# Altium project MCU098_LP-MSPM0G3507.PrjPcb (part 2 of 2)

## Sheet MCU098_04_XDS110-ET_EnergyTrace.SchDoc: XDS110-ET EnergyTrace
size 431 x 279 mm; Date: Not shown in title block; ApprovedBy: Not shown in title block; CheckedBy: Not shown in title block; Author: Not shown in title block; CompanyName: Not shown in title block; DrawnBy: Johnson He; Engineer: Not shown in title block; Organization: Not shown in title block; Address1: Not shown in title block; Address2: Not shown in title block; Address3: Not shown in title block; Address4: Not shown in title block; DocumentNumber: 2; Revision: Use project parameter SCH_Rev; SheetNumber: 4; SheetTotal: 7; PageSetup: Record=PageOptions¦CenterHorizontal=True¦CenterVertical=True¦PrintScale=1.00¦XCorrection=1.00¦YCorrection=1.00¦PrintKind=0¦BorderSize=5000000¦LeftOffset=0¦BottomOffset=0¦Orientation=2¦PaperLength=1000¦PaperWidth=1000¦Scale=100¦PaperSource=15¦PrintQuality=600¦MediaType=1¦DitherType=10¦PaperKind=Letter¦PrintScaleMode=1
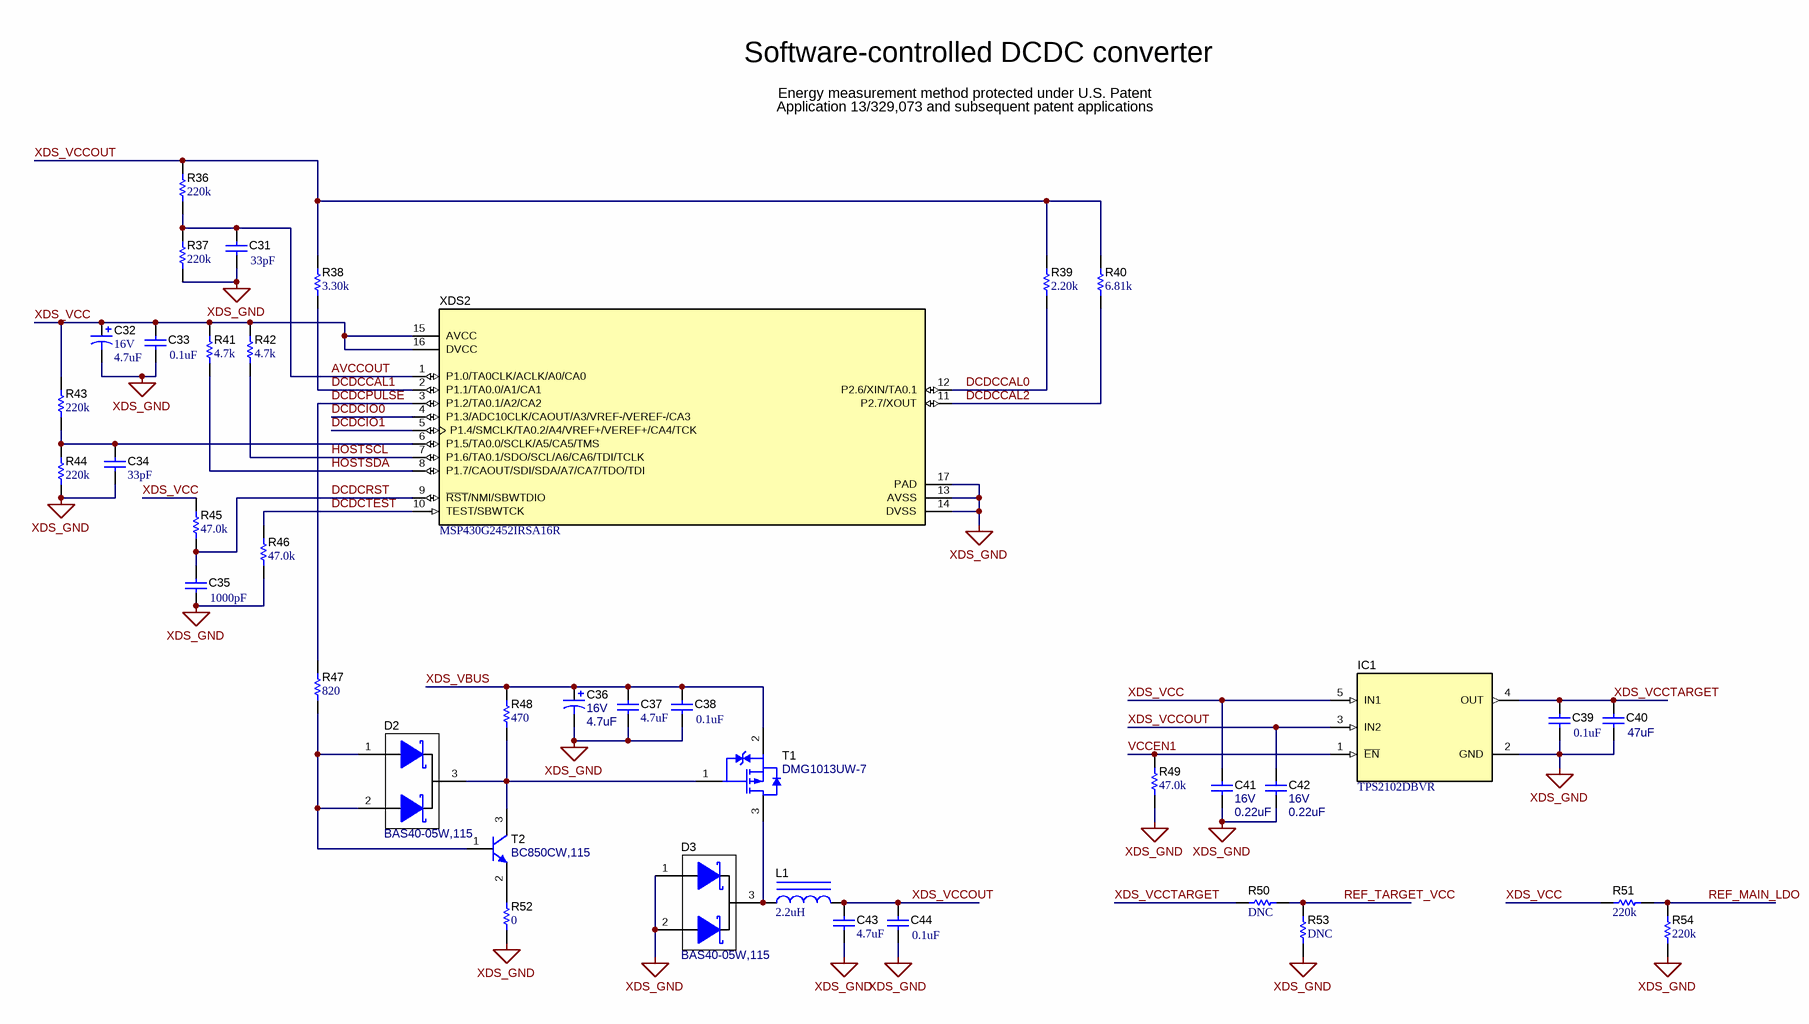
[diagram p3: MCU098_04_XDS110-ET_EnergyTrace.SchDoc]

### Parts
C31  ValueDisplayed: 33pF  [0402]  (hidden comment: GRM1555C1H330JA01D)
C32  VDC_V: 16V  ValueDisplayed: 4.7uF  [3216-18]  (hidden comment: TAJA475K016RNJ)
C33  ValueDisplayed: 0.1uF  [0402]  (hidden comment: GRM155R70J104KA01D)
C34  ValueDisplayed: 33pF  [0402]  (hidden comment: GRM1555C1H330JA01D)
C35  ValueDisplayed: 1000pF  [0402]  (hidden comment: GCM155R71H102KA37D)
C36  VDC_V: 16V  ValueDisplayed: 4.7uF  [3216-18]  (hidden comment: TAJA475K016RNJ)
C37  ValueDisplayed: 4.7uF  [0603]  (hidden comment: GRM188R61C475KAAJ)
C38  ValueDisplayed: 0.1uF  [0402]  (hidden comment: GRM155R70J104KA01D)
C39  ValueDisplayed: 0.1uF  [0402]  (hidden comment: GRM155R70J104KA01D)
C40  ValueDisplayed: 47uF  [0603]  (hidden comment: GRM188R60J476ME15D)
C41  VDC_V: 16V  ValueDisplayed: 0.22uF  [0402]  (hidden comment: GRM155R71C224KA12D)
C42  VDC_V: 16V  ValueDisplayed: 0.22uF  [0402]  (hidden comment: GRM155R71C224KA12D)
C43  ValueDisplayed: 4.7uF  [0603]  (hidden comment: GRM188R61C475KAAJ)
C44  ValueDisplayed: 0.1uF  [0402]  (hidden comment: GRM155R70J104KA01D)
D2  BAS40-05W,115  [SOT-323]
D3  BAS40-05W,115  [SOT-323]
IC1  TPS2102DBVR  [DBV0005A_N]
L1  ValueDisplayed: 2.2uH  [CBC2518]  (hidden comment: CBC2518T2R2M)
R36  ValueDisplayed: 220k  [0402]  (hidden comment: RC0402FR-07220KL)
R37  ValueDisplayed: 220k  [0402]  (hidden comment: RC0402FR-07220KL)
R38  ValueDisplayed: 3.30k  [0402]  (hidden comment: ERJ-2RKF3301X)
R39  ValueDisplayed: 2.20k  [0402]  (hidden comment: CRCW04022K20FKED)
R40  ValueDisplayed: 6.81k  [0402]  (hidden comment: CRCW04026K81FKED)
R41  ValueDisplayed: 4.7k  [0402]  (hidden comment: CRCW04024K70JNED)
R42  ValueDisplayed: 4.7k  [0402]  (hidden comment: CRCW04024K70JNED)
R43  ValueDisplayed: 220k  [0402]  (hidden comment: RC0402FR-07220KL)
R44  ValueDisplayed: 220k  [0402]  (hidden comment: RC0402FR-07220KL)
R45  ValueDisplayed: 47.0k  [0402]  (hidden comment: RC0402FR-0747KL)
R46  ValueDisplayed: 47.0k  [0402]  (hidden comment: RC0402FR-0747KL)
R47  ValueDisplayed: 820  [0402]  (hidden comment: RC0402FR-07820RL)
R48  ValueDisplayed: 470  [0402]  (hidden comment: CRCW0402470RJNED)
R49  ValueDisplayed: 47.0k  [0402]  (hidden comment: RC0402FR-0747KL)
R50  ValueDisplayed: DNC  [0402]  (hidden comment: RC0402FR-07220KL)  (no BOM)
R51  ValueDisplayed: 220k  [0402]  (hidden comment: RC0402FR-07220KL)
R52  ValueDisplayed: 0  [0603]  (hidden comment: RC0603JR-070RL)
R53  ValueDisplayed: DNC  [0402]  (hidden comment: RC0402FR-07220KL)  (no BOM)
R54  ValueDisplayed: 220k  [0402]  (hidden comment: RC0402FR-07220KL)
T1  DMG1013UW-7  [SOT-323]
T2  BC850CW,115  [SOT-323]
XDS2  MSP430G2452IRSA16R  [RSA0016B]

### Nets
XDS_GND: C31.2 C32.2(-) C33.2 C34.2 C35.2 C36.2(-) C37.1 C38.2 C39.2 C40.2 C41.2 C42.2 C43.1 C44.2 D3.1(A) D3.2(A) IC1.2(GND) R37.1 R44.1 R46.1 R49.1 R52.1 R53.1 R54.1 XDS2.13(AVSS) XDS2.14(DVSS) XDS2.17(PAD)
XDS_VCC: C32.1(+) C33.1 C41.1 IC1.5(IN1) R41.2 R42.2 R43.2 R45.2 R51.2 XDS2.15(AVCC) XDS2.16(DVCC)
AVCCOUT: C31.1 R36.1 R37.2 XDS2.1(P1.0/TA0CLK/ACLK/A0/CA0)
DCDCCAL0: R39.1 XDS2.12(P2.6/XIN/TA0.1)
DCDCCAL1: R38.1 XDS2.2(P1.1/TA0.0/A1/CA1)
DCDCCAL2: R40.1 XDS2.11(P2.7/XOUT)
DCDCIO0: XDS2.4(P1.3/ADC10CLK/CAOUT/A3/VREF-/VEREF-/CA3)
DCDCIO1: XDS2.5(P1.4/SMCLK/TA0.2/A4/VREF+/VEREF+/CA4/TCK)
DCDCPULSE: R47.2 XDS2.3(P1.2/TA0.1/A2/CA2)
DCDCRST: C35.1 R45.1 XDS2.9(~{RST}/NMI/SBWTDIO)
DCDCTEST: R46.2 XDS2.10(TEST/SBWTCK)
HOSTSCL: R42.1 XDS2.7(P1.6/TA0.1/SDO/SCL/A6/CA6/TDI/TCLK)
HOSTSDA: R41.1 XDS2.8(P1.7/CAOUT/SDI/SDA/A7/CA7/TDO/TDI)
REF_MAIN_LDO: R51.1 R54.2
REF_TARGET_VCC: R50.1 R53.2
VCCEN1: IC1.1(~{EN}) R49.2
XDS_VBUS: C36.1(+) C37.2 C38.1 R48.2 T1.2(S)
XDS_VCCOUT: C42.1 C43.2 C44.1 IC1.3(IN2) L1.2 R36.2 R38.2 R39.2 R40.2
XDS_VCCTARGET: C39.1 C40.1 IC1.4(OUT) R50.2
NetC34_1: C34.1 R43.1 R44.2 XDS2.6(P1.5/TA0.0/SCLK/A5/CA5/TMS)
NetD2_1: D2.1(A) D2.2(A) R47.1 T2.1(B)
NetD2_3: D2.3(K) R48.1 T1.1(G) T2.3(C)
NetD3_3: D3.3(K) L1.1 T1.3(D)
NetR52_2: R52.2 T2.2(E)

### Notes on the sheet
- Software-controlled DCDC converter
- Energy measurement method protected under U.S. Patent
- Application 13/329,073 and subsequent patent applications

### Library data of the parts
C31 C34 = CMP-0006454-1: CAP, CERM, 33 pF, 50 V, +/- 5%, C0G/NP0, 0402; Manufacturer: MuRata; TaMin_C: -55°C; Polarized: N; SizeAreaWB_mm2: 3; Value1: Unknown; U/M: EA; Value: 33pF; TaMax_C: 125°C; SizeZ_mm: 0.6; SizeX_mm: 1; SizeY_mm: 0.5; Value2: 50V; AEC Category: Q200
C32 C36 = CMP-0011480-1: CAP, TA, 4.7 uF, 16 V, +/- 10%, 4 ohm, SMD; Manufacturer: AVX; TaMin_C: -55°C; ESR_ohm: 4; Polarized: Y; SizeAreaWB_mm2: 10.92; Value1: 4 ohm; U/M: EA; Value: 4.7uF; TaMax_C: 125°C; SizeZ_mm: 1.8; SizeX_mm: 3.2; SizeY_mm: 1.6; SizeArea_mm2: 5.12; CompType: Capacitor; AEC Qualified: N; Cap_F: 4.7µF; AEC Category: Q200
C33 C38 C39 C44 = CMP-0006623-2: CAP, CERM, 0.1 uF, 6.3 V, +/- 10%, X7R, 0402; Manufacturer: MuRata; TaMin_C: -55°C; Polarized: N; SizeAreaWB_mm2: 3; Value1: Unknown; U/M: EA; Value: 0.1uF; TaMax_C: 125°C; SizeZ_mm: 0.6; SizeX_mm: 1; SizeY_mm: 0.5; Value2: 6.3V; Cap_F: 100nF; AEC Category: Q200
C35 = CMP-0006354-2: CAP, CERM, 1000 pF, 50 V, +/- 10%, X7R, AEC-Q200 Grade 1, 0402; Manufacturer: MuRata; TaMin_C: -55°C; Polarized: N; SizeAreaWB_mm2: 3; Value1: Unknown; U/M: EA; Value: 1000pF; TaMax_C: 125°C; SizeZ_mm: 0.6; SizeX_mm: 1; SizeY_mm: 0.5; Value2: 50V; AEC Qualified: Y; Cap_F: 1nF; AEC Category: Q200
C37 C43 = CMP-0007341-4: CAP, CERM, 4.7 uF, 16 V, +/- 10%, X5R, 0603; Manufacturer: MuRata; TaMin_C: -55°C; Polarized: N; SizeAreaWB_mm2: 4.68; Value1: Unknown; U/M: EA; Value: 4.7uF; TaMax_C: 85°C; SizeZ_mm: 1; SizeX_mm: 1.6; SizeY_mm: 0.8; Value2: 16V; SizeArea_mm2: 1.28; Cap_F: 4.7µF; AEC Category: Q200
C40 = CMP-0007313-1: CAP, CERM, 47 uF, 6.3 V, +/- 20%, X5R, 0603; Manufacturer: MuRata; TaMin_C: -55°C; Polarized: N; SizeAreaWB_mm2: 4.68; Value1: Unknown; U/M: EA; Value: 47uF; TaMax_C: 85°C; SizeZ_mm: 1; SizeX_mm: 1.6; SizeY_mm: 0.8; Value2: 6.3V; SizeArea_mm2: 1.28; Cap_F: 47µF; AEC Category: Q200
C41 C42 = CMP-0006648-1: CAP, CERM, 0.22 uF, 16 V, +/- 10%, X7R, 0402; Manufacturer: MuRata; TaMin_C: -55°C; Polarized: N; SizeAreaWB_mm2: 3; Value1: Unknown; U/M: EA; Value: 0.22uF; TaMax_C: 125°C; SizeZ_mm: 0.6; SizeX_mm: 1; SizeY_mm: 0.5; Cap_F: 220nF; AEC Category: Q200
D2 D3 = CMP-0028883-1: Diode, Schottky, 40 V, 0.12 A, AEC-Q101, SOT-323; Manufacturer: Nexperia; Io_A: 120mA; Green_Lifecycle: Not Set; SizeAreaWB_mm2: 10.24; Vr_V: 40V; Green_REACh: Incomplete; Value1: 0.12A; TJmax_C: 150°C; U/M: EA; Value: 40V; SizeZ_mm: 1.1; SizeX_mm: 2.2; Vf_V: 1V; SizeArea_mm2: 4.84; AEC Qualified: Y; AEC Category: Q101
IC1 = CMP-0074212-1: 2.7-4V Dual In/Single Out MOSFET, 0.5A Main/0.1A Aux Input, Act-Low Enable, Comm. Temp., DBV0005A (SOT-23-5); Alternate PartNumber: TPS2102DBVT; Alternate Manufacturer: Texas Instruments; SizeAreaWB_mm2: 14.82; U/M: EA; SizeZ_mm: 1.45; SizeX_mm: 2.8; SizeY_mm: 2.9; SizeArea_mm2: 8.12; CompType: IC
L1 = CMP-0059590-1: Inductor, Wirewound, Ceramic, 2.2 uH, 0.89 A, 0.13 ohm, SMD; Manufacturer: Taiyo Yuden; Isat: 0.89A @ 30% inductance drop; Irms: 1.1A @ 40C rise; Green_Lifecycle: Active; SizeAreaWB_mm2: 9.8; DCR_ohm: 0.13; Green_REACh: Passed; Value: 2.2uH; Imax_A: 890mA; SizeZ_mm: 1.8; SizeX_mm: 2.5; Value2: 0.89A; SizeArea_mm2: 4.5; Ind_H: 2.2µH; AEC Qualified: N; AEC Category: Q200
R36 R37 R43 R44 R51 R54 = CMP-0026728-1: RES, 220 k, 1%, 0.0625 W, 0402; Manufacturer: Yageo America; Power_W: 62.5mW; TempCo: 100 ppm/C; U/M: EA; Value: 220k; SizeX_mm: 1; SizeY_mm: 0.5; SizeZ_mm: 0.6; AEC Qualified: N; VDC_V: 50V; AEC Category: Q200
R38 = CMP-0026695-1: RES, 3.30 k, 1%, 0.1 W, AEC-Q200 Grade 0, 0402; Manufacturer: Panasonic; Power_W: 100mW; TempCo: 100 ppm/C; Value_Code: 3k30; U/M: EA; Value: 3.30k; Res_ohm: 3.3k; SizeX_mm: 1; SizeY_mm: 0.5; SizeZ_mm: 0.6; Value2: 0.1W; AEC Qualified: Y; VDC_V: 50V; AEC Grade: 0; AEC Category: Q200
R39 = CMP-0026231-1: RES, 2.20 k, 1%, 0.063 W, 0402; Manufacturer: Vishay-Dale; Power_W: 63mW; TempCo: 100 ppm/C; Value_Code: 2k20; U/M: EA; Value: 2.20k; Res_ohm: 2.2k; SizeX_mm: 1; SizeY_mm: 0.5; SizeZ_mm: 0.6; Value2: 0.063W; AEC Category: Q200
R40 = CMP-0026517-1: RES, 6.81 k, 1%, 0.063 W, 0402; Manufacturer: Vishay-Dale; Power_W: 63mW; TempCo: 100 ppm/C; Value_Code: 6k81; U/M: EA; Value: 6.81k; EIA_Code: E96; SizeX_mm: 1; SizeY_mm: 0.5; SizeZ_mm: 0.6; Value2: 0.063W; VDC_V: 50V; AEC Category: Q200
R41 R42 = CMP-0026938-1: RES, 4.7 k, 5%, 0.063 W, 0402; Manufacturer: Vishay-Dale; Power_W: 63mW; TempCo: 200 ppm/C; Value_Code: 4k70; U/M: EA; Value: 4.7k; EIA_Code: E24; SizeX_mm: 1; SizeY_mm: 0.5; SizeZ_mm: 0.6; Value2: 0.063W; VDC_V: 50V; AEC Category: Q200
R45 R46 R49 = CMP-0026737-1: RES, 47.0 k, 1%, 0.0625 W, 0402; Manufacturer: Yageo America; Power_W: 62.5mW; TempCo: 100 ppm/C; Value_Code: 47k0; U/M: EA; Value: 47.0k; Res_ohm: 47k; SizeX_mm: 1; SizeY_mm: 0.5; SizeZ_mm: 0.6; AEC Qualified: N; VDC_V: 50V; AEC Category: Q200
R47 = CMP-0026743-1: RES, 820, 1%, 0.063 W, 0402; Manufacturer: Yageo America; Power_W: 63mW; TempCo: 100 ppm/C; Value_Code: 820R; U/M: EA; Value: 820; SizeX_mm: 1; SizeY_mm: 0.5; SizeZ_mm: 0.6; Value2: 0.063W; AEC Qualified: N; VDC_V: 50V; AEC Category: Q200
R48 = CMP-0026934-1: RES, 470, 5%, 0.063 W, 0402; Manufacturer: Vishay-Dale; Power_W: 63mW; TempCo: 200 ppm/C; Value_Code: 470R; U/M: EA; Value: 470; EIA_Code: E24; SizeX_mm: 1; SizeY_mm: 0.5; SizeZ_mm: 0.6; Value2: 0.063W; VDC_V: 50V; AEC Category: Q200
R50 R53 = CMP-0026728-1: RES, 220 k, 1%, 0.0625 W, 0402; Manufacturer: Yageo America; Power_W: 62.5mW; TempCo: 100 ppm/C; Value_Code: 220k; U/M: EA; Value: 220k; SizeX_mm: 1; SizeY_mm: 0.5; SizeZ_mm: 0.6; AEC Qualified: N; VDC_V: 50V; AEC Category: Q200
R52 = CMP-0025885-5: RES, 0, 5%, 0.1 W, 0603; Manufacturer: Yageo; Power_W: 100mW; TempCo: 200 ppm/C; Value_Code: 0000; Value: 0; EIA_Code: E24; SizeX_mm: 1.6; SizeZ_mm: 1; Value2: 0.1W; SizeArea_mm2: 1.28; AEC Qualified: N; VDC_V: 75V; AEC Category: Q200; SizeY_mm: 0.8; SizeAreaWB_mm2: 4.68
T1 = CMP-0000035-1: MOSFET, P-CH, -20 V, -0.82 A, SOT-323; Alternate Manufacturer: None; Manufacturer: Diodes Inc.; SizeZ_mm: 1.1; ChType: P; Value2: 0.622 nC; Value1: 0.7; VdsMax_V: -20V; SizeX_mm: 2.2; Vgs_V: -6V; Value: -20V; Rdson45_ohm: 0.75; SizeArea_mm2: 4.84; AEC Category: Q101; IdsMax_A: -820mA; SizeAreaWB_mm2: 10.24; U/M: EA; QgTyp_nC: 0.622
T2 = CMP-0000466-1: Transistor, NPN, 45 V, 0.1 A, SOT-323; Manufacturer: NXP Semiconductor; TaMax_C: 150°C; Value2: 800; Value1: 0.1 A; Vcesat1_V: 250mV; SizeX_mm: 2.2; TaMin_C: -65°C; IcRated_A: 100mA; CompType: BJT; SizeZ_mm: 1.1; Value: 45 V; SizeArea_mm2: 4.84; NPN: 1; Vceo_V: 45V; PNP: 0; AEC Category: Q101; SizeAreaWB_mm2: 10.24; U/M: EA
XDS2 = CMP-0039611-2: MSP430G2x52, MSP430G2x12 Mixed Signal Microcontroller, RSA0016B (VQFN-16); Manufacturer: Texas Instruments; Alternate PartNumber: MSP430G2452IRSA16T; Eco-Plan: Green (RoHS & no Sb/Br); ADC: 10-bit SAR; SRAM(B): 256; Temp Sensor: Yes; Frequency(MHz): 16; ADC Channels: 8; Timers - 16-bit: 1; AEC Category: Q200; AEC Qualified: N; CompType: IC; Rating: Catalog; SizeAreaWB_mm2: 25; SizeX_mm: 4

## Sheet MCU098_05_XDS110_Target_Interface.SchDoc: XDS110-ET Interface
size 431 x 279 mm; DrawnBy: Johnson He; SheetNumber: 5; SheetTotal: 7; PageSetup: Record=PageOptions¦CenterHorizontal=True¦CenterVertical=True¦PrintScale=0.97¦XCorrection=1.00¦YCorrection=1.00¦PrintKind=0¦BorderSize=5000000¦LeftOffset=0¦BottomOffset=0¦Orientation=2¦PaperLength=1000¦PaperWidth=1000¦Scale=100¦PaperSource=15¦PrintQuality=600¦MediaType=1¦DitherType=10¦PaperKind=Letter¦PrintScaleMode=1
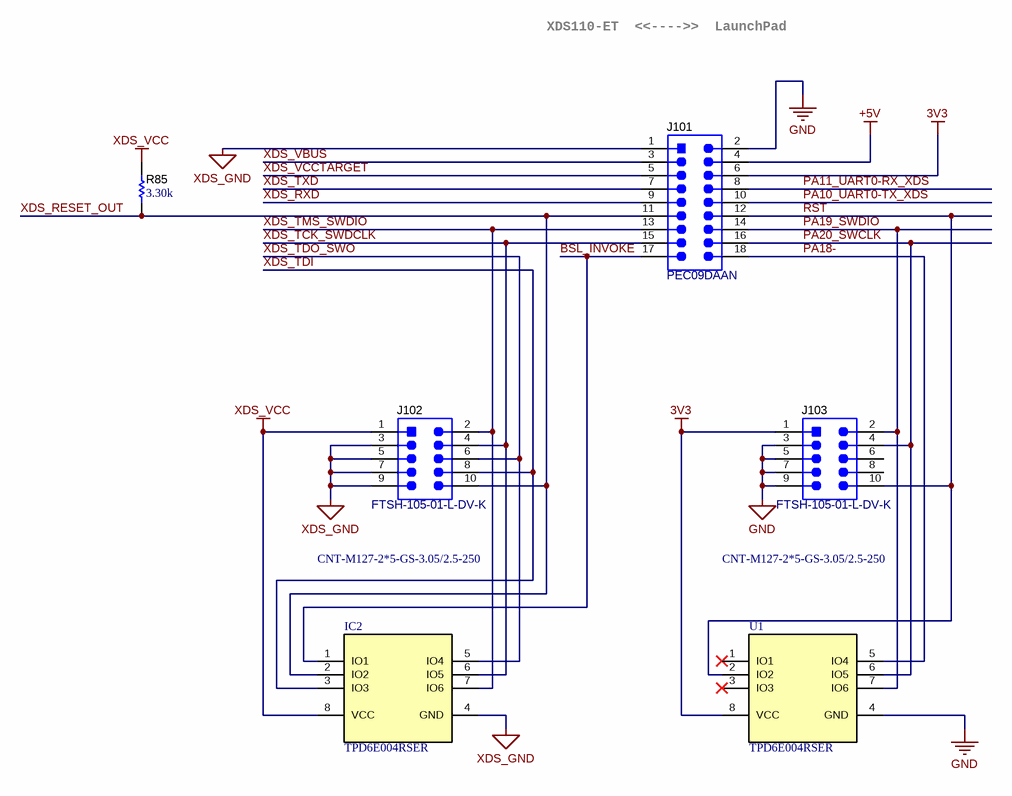
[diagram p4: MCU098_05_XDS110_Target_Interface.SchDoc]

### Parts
IC2  TPD6E004RSER  [RSE0008A]
J101  PEC09DAAN  [Sullins_PxC09DAAN]
J102  FTSH-105-01-L-DV-K  [Samtec_FTSH-105-01-x-DV-K]
J103  FTSH-105-01-L-DV-K  [Samtec_FTSH-105-01-x-DV-K]
R85  ValueDisplayed: 3.30k  [0402]  (hidden comment: ERJ-2RKF3301X)
U1  TPD6E004RSER  [RSE0008A]

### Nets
3V3: J101.6 J103.1 U1.8(VCC)
+5V: J101.4
GND: J101.2 J103.3 J103.5 J103.7 J103.9 U1.4(GND)
XDS_GND: IC2.4(GND) J101.1 J102.3 J102.5 J102.7 J102.9
XDS_VCC: IC2.8(VCC) J102.1 R85.2
BSL_INVOKE: IC2.1(IO1) J101.17
PA10_UART0-TX_XDS: J101.10
PA11_UART0-RX_XDS: J101.8
PA18-: J101.18 U1.5(IO4)
PA19_SWDIO: J101.14 J103.2 U1.7(IO6)
PA20_SWCLK: J101.16 J103.4 U1.6(IO5)
~{RST}: J101.12 J103.10 U1.2(IO2)
XDS_RESET_OUT: IC2.2(IO2) J101.11 J102.10 R85.1
XDS_RXD: J101.9
XDS_TCK_SWDCLK: IC2.6(IO5) J101.15 J102.4
XDS_TDI: IC2.3(IO3) J102.8
XDS_TDO_SWO: IC2.5(IO4) J102.6
XDS_TMS_SWDIO: IC2.7(IO6) J101.13 J102.2
XDS_TXD: J101.7
XDS_VBUS: J101.3
XDS_VCCTARGET: J101.5

Not connected (* = marked no-connect by the designer): J103 6 8; U1 1(IO1)* 3(IO3)*

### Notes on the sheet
- XDS110-ET  <<---->>  LaunchPad
- CNT-M127-2*5-GS-3.05/2.5-250

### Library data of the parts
IC2 U1 = CMP-0043125-2: Low-Capacitance + / - 15 kV ESD Protection Array for High-Speed Data Interfaces, 6 Channels, -40 to +85 degC, 8-pin UQFN (RSE), Green (RoHS & no Sb/Br); Manufacturer: Texas Instruments; IO Leakage Current(nA): 1; IO Capacitance(Typ)(pF): 1.6; 1394 / Firewire: TRUE; SubFamily: ESD Solution; Breakdown Voltage(Min)(V): 6; IEC 61000-4-2 Air-Gap(+/- kV): 12; IEC 61000-4-2 Contact(+/- kV): 8
J101 = CMP-0054622-1: Header, 2.54mm, 9x2, Tin, TH; Manufacturer: Sullins Connector Solutions; CNHeader: TRUE; Current_A: 3A; Shrouded: N; Gender: Male; Row_Count: 2; RowSpacing_mm: 2.54; CT: FALSE; Cert_UL: Y
J102 J103 = CMP-0075634-1: Header(Shrouded), 1.27mm, 5x2, Gold, SMT; Manufacturer: Samtec; Pitch_mm: 1.27; Gender: Male; Cert_CSA: Y; Current_A: 3.3A; CT: False; Row_Count: 2
R85 = CMP-0026695-1: as R38 on sheet MCU098_04_XDS110-ET_EnergyTrace

## Sheet MCU098_06_XDS110-ET_USB_Power.SchDoc: XDS110-ET USB Power
size 431 x 279 mm; DrawnBy: Johnson He; SheetNumber: 6; SheetTotal: 7; PageSetup: Record=PageOptions¦CenterHorizontal=True¦CenterVertical=True¦PrintScale=0.97¦XCorrection=1.00¦YCorrection=1.00¦PrintKind=0¦BorderSize=5000000¦LeftOffset=0¦BottomOffset=0¦Orientation=2¦PaperLength=1000¦PaperWidth=1000¦Scale=100¦PaperSource=15¦PrintQuality=600¦MediaType=1¦DitherType=10¦PaperKind=Letter¦PrintScaleMode=1
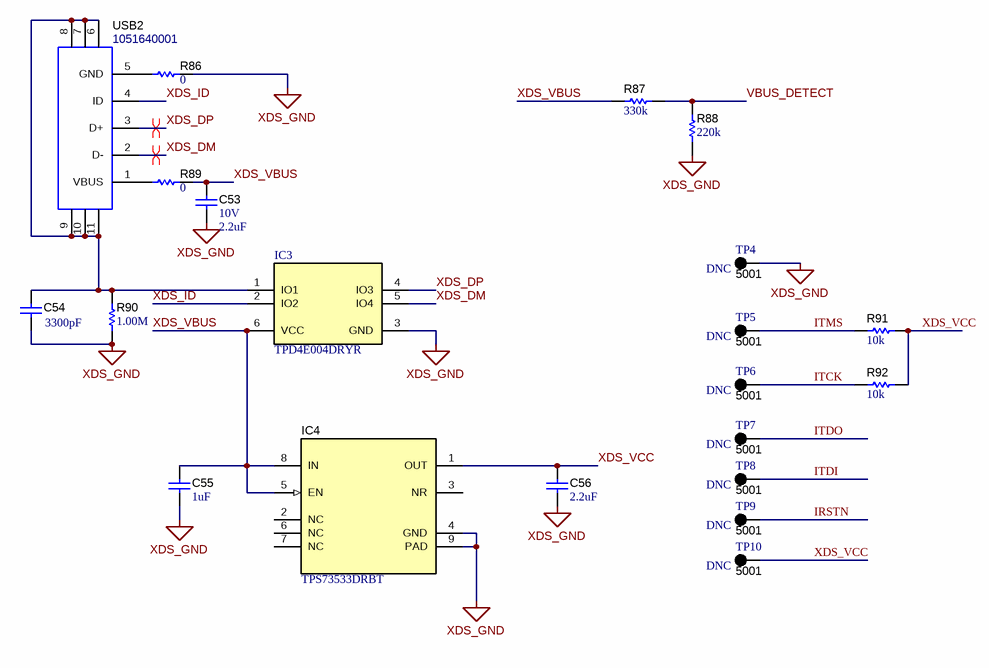
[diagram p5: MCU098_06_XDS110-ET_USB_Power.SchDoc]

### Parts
C53  VDC_V: 10V  ValueDisplayed: 2.2uF  [0603]  (hidden comment: C0603C225K8PACTU)
C54  ValueDisplayed: 3300pF  [0402]  (hidden comment: GRM155R71H332KA01D)
C55  ValueDisplayed: 1uF  [0402]  (hidden comment: C1005X5R1E105K050BC)
C56  ValueDisplayed: 2.2uF  [0402]  (hidden comment: GRM155R60J225KE95D)
IC3  TPD4E004DRYR  [DRY0006A]
IC4  TPS73533DRBT  [DRB0008A]
R86  ValueDisplayed: 0  [0603]  (hidden comment: RC0603JR-070RL)
R87  ValueDisplayed: 330k  [0402]  (hidden comment: RC0402FR-07330KL)
R88  ValueDisplayed: 220k  [0402]  (hidden comment: RC0402FR-07220KL)
R89  ValueDisplayed: 0  [0603]  (hidden comment: RC0603JR-070RL)
R90  ValueDisplayed: 1.00M  [0402]  (hidden comment: CRCW04021M00FKED)
R91  ValueDisplayed: 10k  [0402]  (hidden comment: CRCW040210K0JNED)
R92  ValueDisplayed: 10k  [0402]  (hidden comment: CRCW040210K0JNED)
TP4  5001  Display: DNC  [Keystone5001]  (no BOM)
TP5  5001  Dispaly: DNC  [Keystone5001]  (no BOM)
TP6  5001  Dispaly: DNC  [Keystone5001]  (no BOM)
TP7  5001  Dispaly: DNC  [Keystone5001]  (no BOM)
TP8  5001  Dispaly: DNC  [Keystone5001]  (no BOM)
TP9  5001  Dispaly: DNC  [Keystone5001]  (no BOM)
TP10  5001  Dispaly: DNC  [Keystone5001]  (no BOM)
USB2  1051640001  [Molex_1051640001]

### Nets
XDS_GND: C53.2 C54.2 C55.2 C56.2 IC3.3(GND) IC4.4(GND) IC4.9(PAD) R86.2 R88.1 R90.1 TP4.1
XDS_VCC: C56.1 IC4.1(OUT) R91.1 R92.1 TP10.1
IRSTN: TP9.1
ITCK: R92.2 TP6.1
ITDI: TP8.1
ITDO: TP7.1
ITMS: R91.2 TP5.1
VBUS_DETECT: R87.2 R88.2
XDS_DM: IC3.5(IO4) USB2.2(D-)
XDS_DP: IC3.4(IO3) USB2.3(D+)
XDS_ID: IC3.2(IO2) USB2.4(ID)
XDS_VBUS: C53.1 C55.1 IC3.6(VCC) IC4.5(EN) IC4.8(IN) R87.1 R89.2
NetC54_1: C54.1 IC3.1(IO1) R90.2 USB2.6 USB2.7 USB2.8 USB2.9 USB2.10 USB2.11
NetR86_1: R86.1 USB2.5(GND)
NetR89_1: R89.1 USB2.1(VBUS)

Not connected (* = marked no-connect by the designer): IC4 2(NC) 3(NR) 6(NC) 7(NC)

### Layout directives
differential pair: XDS_DM, XDS_DP

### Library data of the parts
C53 = CMP-0006906-5: CAP, CERM, 2.2 uF, 10 V, +/- 10%, X5R, 0603; Manufacturer: Kemet; TaMin_C: -55°C; Polarized: N; SizeAreaWB_mm2: 4.68; Value1: Unknown; U/M: EA; Value: 2.2uF; TaMax_C: 85°C; SizeZ_mm: 1; SizeX_mm: 1.6; SizeY_mm: 0.8; SizeArea_mm2: 1.28; Cap_F: 2.2µF; AEC Category: Q200
C54 = CMP-0006688-2: CAP, CERM, 3300 pF, 50 V, +/- 10%, X7R, 0402; Manufacturer: MuRata; TaMin_C: -55°C; Polarized: N; SizeAreaWB_mm2: 3; Value1: Unknown; U/M: EA; Value: 3300pF; TaMax_C: 125°C; SizeZ_mm: 0.6; SizeX_mm: 1; SizeY_mm: 0.5; Value2: 50V; Cap_F: 3.3nF; AEC Category: Q200
C55 = CMP-0006276-2: CAP, CERM, 1 uF, 25 V, +/- 10%, X5R, 0402; Manufacturer: TDK; TaMin_C: -55°C; Polarized: N; SizeAreaWB_mm2: 3; Value1: Unknown; U/M: EA; Value: 1uF; TaMax_C: 80°C; SizeZ_mm: 0.6; SizeX_mm: 1; SizeY_mm: 0.5; Value2: 25V; Cap_F: 1µF; AEC Category: Q200
C56 = CMP-0006543-2: CAP, CERM, 2.2 uF, 6.3 V, +/- 10%, X5R, 0402; Manufacturer: MuRata; TaMin_C: -55°C; Polarized: N; SizeAreaWB_mm2: 3; Value1: Unknown; U/M: EA; Value: 2.2uF; TaMax_C: 85°C; SizeZ_mm: 0.6; SizeX_mm: 1; SizeY_mm: 0.5; Value2: 6.3V; Cap_F: 2.2µF; AEC Category: Q200
IC3 = CMP-0043115-1: ESD-Protection Array for High-Speed Data Interfaces, 4 Channels, -40 to +85 degC, 6-pin SON (DRY), Green (RoHS & no Sb/Br); Manufacturer: Texas Instruments; IO Leakage Current(nA): 1; USB High Speed: TRUE; IO Capacitance(Typ)(pF): 1.6; SubFamily: ESD Solution; IEC 61000-4-2 Contact(+/- kV): 8; Breakdown Voltage(Min)(V): 6; IEC 61000-4-2 Air-Gap(+/- kV): 12
IC4 = CMP-0036329-3: 500mA, Adjustable, Low Quiescent Current, Low-Noise, High-PSRR, Single-Output LDO Regulator, DRB0008A (VSON-8); Manufacturer: Texas Instruments; AEC Category: Q200; Vout Adj(Max)(V): 3.3; Vdo(Typ)(mV): 280; SizeY_mm: 3.0; Vin(Max)(V): 6.5; Accuracy(%): 2; Vin(Min)(V): 2.7; SizeAreaWB_mm2: 16.0; SizeZ_mm: 1.0; AEC Qualified: N; SizeArea_mm2: 9.0; Iout(Max)(A): 0.5; Rating: Catalog; Iq(Typ)(mA): 0.04; CompType: IC
R86 R89 = CMP-0025885-5: as R52 on sheet MCU098_04_XDS110-ET_EnergyTrace
R87 = CMP-0026731-1: RES, 330 k, 1%, 0.0625 W, 0402; Manufacturer: Yageo America; Power_W: 62.5mW; TempCo: 100 ppm/C; U/M: EA; Value: 330k; SizeX_mm: 1; SizeY_mm: 0.5; SizeZ_mm: 0.6; AEC Qualified: N; VDC_V: 50V; AEC Category: Q200
R88 = CMP-0026728-1: as R36 on sheet MCU098_04_XDS110-ET_EnergyTrace
R90 = CMP-0026100-1: RES, 1.00 M, 1%, 0.063 W, 0402; Manufacturer: Vishay-Dale; Power_W: 63mW; TempCo: 100 ppm/C; Value_Code: 1M00; U/M: EA; Value: 1.00Meg; EIA_Code: E96; Res_ohm: 1M; SizeX_mm: 1; SizeY_mm: 0.5; SizeZ_mm: 0.6; Value2: 0.063W; VDC_V: 50V; AEC Category: Q200
R91 R92 = CMP-0026825-4: RES, 10 k, 5%, 0.063 W, 0402; Manufacturer: Vishay-Dale; Power_W: 63mW; TempCo: 200 ppm/C; Value_Code: 10k0; U/M: EA; Value: 10k; EIA_Code: E24; SizeX_mm: 1; SizeY_mm: 0.5; SizeZ_mm: 0.6; Value2: 0.063W; VDC_V: 50V; AEC Category: Q200
TP4-TP10 = CMP-0055138-1: Test Point, Miniature, Black, TH; Manufacturer: Keystone; CNHeader: FALSE; Green_Lifecycle: Active; Green_REACh: Passed; ContactFinish: Silver; CT: TRUE
USB2 = CMP-0055311-1: Receptacle, USB 2.0, Micro B, 5 Position, R/A, SMT; Manufacturer: Molex; CNHeader: FALSE; Current_A: 1.8A; Gender: Female; Voltage_V: 30V; Pitch_mm: 0.65; ContactFinish: Gold; CT: TRUE; Cert_UL: Y

## Sheet MCU098_07_Hardware.SchDoc: Hardware
size 431 x 279 mm; Date: Not shown in title block; ApprovedBy: Not shown in title block; CheckedBy: Not shown in title block; Author: Not shown in title block; CompanyName: Not shown in title block; DrawnBy: Johnson He; Engineer: Not shown in title block; Organization: Not shown in title block; Address1: Not shown in title block; Address2: Not shown in title block; Address3: Not shown in title block; Address4: Not shown in title block; DocumentNumber: 1; Revision: Use project parameter SCH_Rev; SheetNumber: 7; SheetTotal: 7; PageSetup: Record=PageOptions¦CenterHorizontal=True¦CenterVertical=True¦PrintScale=1.00¦XCorrection=1.00¦YCorrection=1.00¦PrintKind=0¦BorderSize=5000000¦LeftOffset=0¦BottomOffset=0¦Orientation=2¦PaperLength=1000¦PaperWidth=1000¦Scale=100¦PaperSource=15¦PrintQuality=600¦MediaType=1¦DitherType=10¦PaperKind=Letter¦PrintScaleMode=1
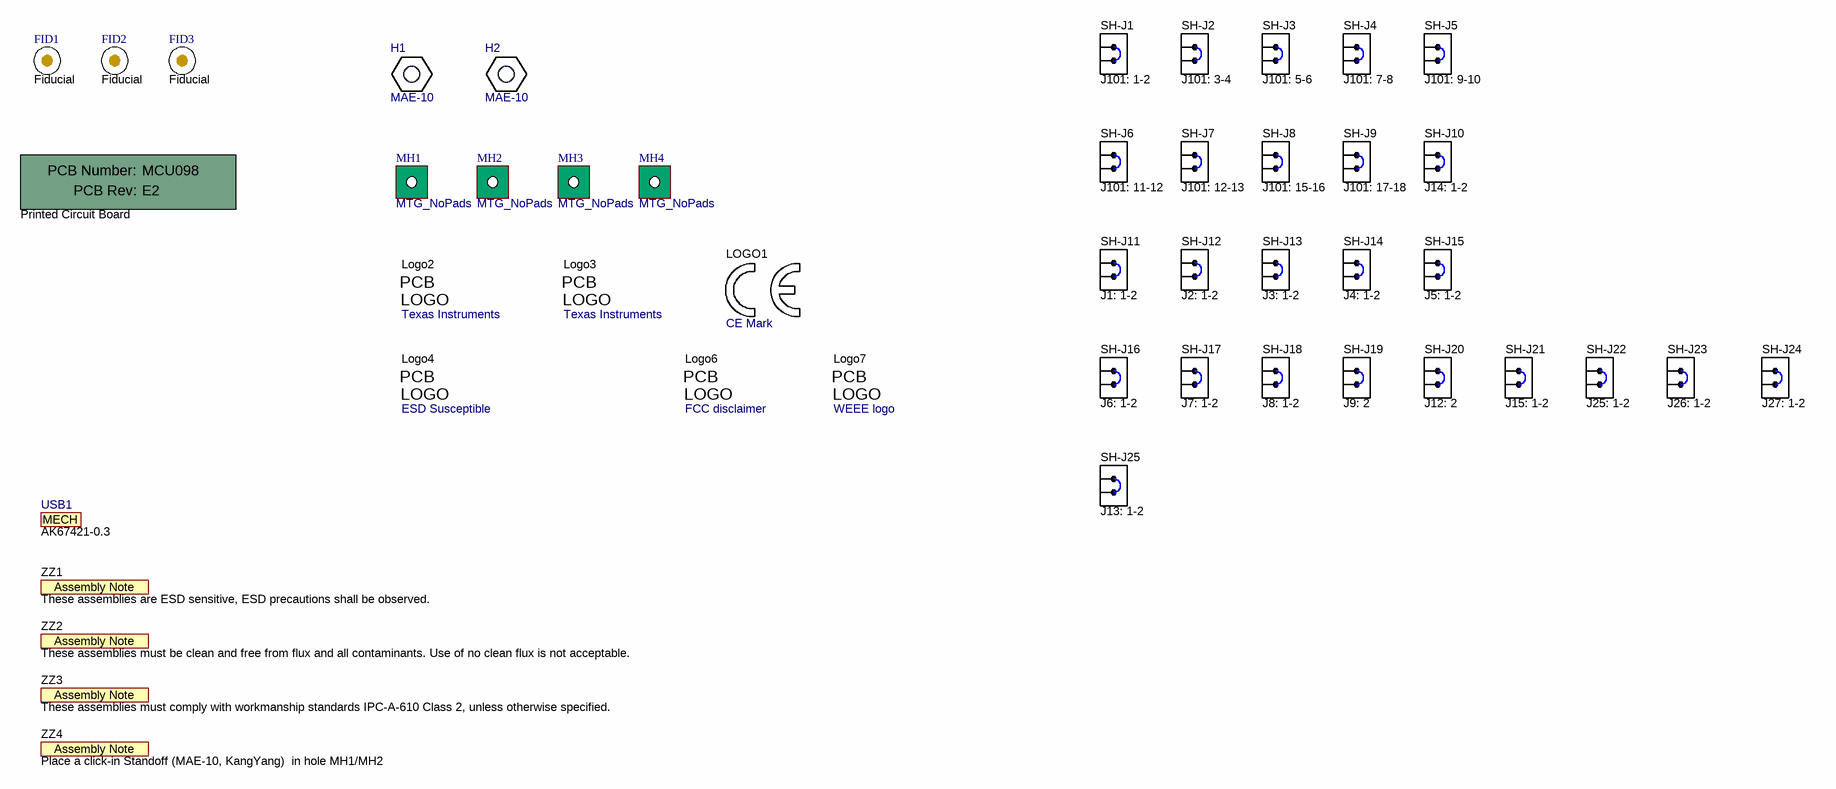
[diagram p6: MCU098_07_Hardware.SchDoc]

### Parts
!PCB1  Printed Circuit Board  (mechanical)
FID1  Fiducial  [Fiducial10-30]
FID2  Fiducial  [Fiducial10-30]
FID3  Fiducial  [Fiducial10-30]
H1  MAE-10  [KY_MAE-10]
H2  MAE-10  [KY_MAE-10]
LOGO1  CE Mark  [CE_Mark_5mm]  (no BOM)
Logo2  Texas Instruments  [TI_Horizontal_Overlay_Small]  (no BOM)
Logo3  Texas Instruments  [TI_Horizontal_Overlay_Medium]  (no BOM)
Logo4  ESD Susceptible  [ESD_Overlay_Large]  (no BOM)
Logo6  FCC disclaimer  [FCC_disclaimer]  (no BOM)
Logo7  WEEE logo  [WEEE_Minimum]  (no BOM)
MH1  MTG_NoPads  [NPTH125mil]  (no BOM)
MH2  MTG_NoPads  [NPTH125mil]  (no BOM)
MH3  MTG_NoPads  [NPTH125mil]  (no BOM)
MH4  MTG_NoPads  [NPTH125mil]  (no BOM)
SH-J1  value J101: 1-2  [SNT-100-BK-G]  (hidden comment: SNT-100-BK-G)
SH-J2  value J101: 3-4  [SNT-100-BK-G]  (hidden comment: SNT-100-BK-G)
SH-J3  value J101: 5-6  [SNT-100-BK-G]  (hidden comment: SNT-100-BK-G)
SH-J4  value J101: 7-8  [SNT-100-BK-G]  (hidden comment: SNT-100-BK-G)
SH-J5  value J101: 9-10  [SNT-100-BK-G]  (hidden comment: SNT-100-BK-G)
SH-J6  value J101: 11-12  [SNT-100-BK-G]  (hidden comment: SNT-100-BK-G)
SH-J7  value J101: 12-13  [SNT-100-BK-G]  (hidden comment: SNT-100-BK-G)
SH-J8  value J101: 15-16  [SNT-100-BK-G]  (hidden comment: SNT-100-BK-G)
SH-J9  value J101: 17-18  [SNT-100-BK-G]  (hidden comment: SNT-100-BK-G)
SH-J10  value J14: 1-2  [SNT-100-BK-G]  (hidden comment: SNT-100-BK-G)
SH-J11  value J1: 1-2  [SNT-100-BK-G]  (hidden comment: SNT-100-BK-G)
SH-J12  value J2: 1-2  [SNT-100-BK-G]  (hidden comment: SNT-100-BK-G)
SH-J13  value J3: 1-2  [SNT-100-BK-G]  (hidden comment: SNT-100-BK-G)
SH-J14  value J4: 1-2  [SNT-100-BK-G]  (hidden comment: SNT-100-BK-G)
SH-J15  value J5: 1-2  [SNT-100-BK-G]  (hidden comment: SNT-100-BK-G)
SH-J16  value J6: 1-2  [SNT-100-BK-G]  (hidden comment: SNT-100-BK-G)
SH-J17  value J7: 1-2  [SNT-100-BK-G]  (hidden comment: SNT-100-BK-G)
SH-J18  value J8: 1-2  [SNT-100-BK-G]  (hidden comment: SNT-100-BK-G)
SH-J19  value J9: 2  [SNT-100-BK-G]  (hidden comment: SNT-100-BK-G)
SH-J20  value J12: 2  [SNT-100-BK-G]  (hidden comment: SNT-100-BK-G)
SH-J21  value J15: 1-2  [SNT-100-BK-G]  (hidden comment: SNT-100-BK-G)
SH-J22  value J25: 1-2  [SNT-100-BK-G]  (hidden comment: SNT-100-BK-G)
SH-J23  value J26: 1-2  [SNT-100-BK-G]  (hidden comment: SNT-100-BK-G)
SH-J24  value J27: 1-2  [SNT-100-BK-G]  (hidden comment: SNT-100-BK-G)
SH-J25  value J13: 1-2  [SNT-100-BK-G]  (hidden comment: SNT-100-BK-G)
USB1  AK67421-0.3  (mechanical)
ZZ1  These assemblies are ESD sensitive, ESD precautions shall be observed.  [AssemblyNote]  (no BOM)
ZZ2  These assemblies must be clean and free from flux and all contaminants. Use of no clean flux is not acceptable.  [AssemblyNote]  (no BOM)
ZZ3  These assemblies must comply with workmanship standards IPC-A-610 Class 2, unless otherwise specified.  [AssemblyNote]  (no BOM)
ZZ4  Place a click-in Standoff (MAE-10, KangYang)  in hole MH1/MH2  [AssemblyNote]  (no BOM)

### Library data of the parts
!PCB1 = CMP-0003618-2: PartNumber: MCU098; Manufacturer: Any
FID1-FID3 = CMP-0077181-1: Fiducial mark.  There is nothing to buy or mount.
H1 H2 = CMP-0077978-1: Spacer Support, Nylon 66; Manufacturer: Kang Yang; CompType: Standoff
LOGO1 = CMP-0074844-1: SymbolCreator: a0412235
Logo2 Logo3 = CMP-0074838-1: Texas Instrument Corporate Signature; SymbolCreator: a0412235; Lib Reference: TI_Logo
Logo4 = CMP-0074840-1: ESD Susceptible Symbol; SymbolCreator: a0412235; Lib Reference: ESD_Susceptible
Logo6 = CMP-0074847-1: FCC_disclaimer
Logo7 = CMP-0074769-1
MH1-MH4 = CMP-0078424-2: PCB Mounting Hole, No Pad; Manufacturer: Any; Key: Mounting Hole (non-standard) No Pad
SH-J1-SH-J25 = CMP-0003623-3: Shunt, 100mil, Gold plated, Black; Alternate PartNumber: 969102-0000-DA; Manufacturer: Samtec; Alternate Manufacturer: 3M
USB1 = CMP-0077983-1: Cable, USB-A to micro USB-B, 0.3 m; Manufacturer: Assman WSW
ZZ1-ZZ4 = AssemblyNote: SymbolCreator: codlsc

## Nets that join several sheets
3V3: MCU098_01_MSPM0G3507_Target_Device (10 pins), MCU098_02_BoosterPack_Connectors (7 pins), MCU098_05_XDS110_Target_Interface (J101.6 J103.1 U1.8)
+5V: MCU098_01_MSPM0G3507_Target_Device (J10.1 R12.2 R16.2), MCU098_02_BoosterPack_Connectors (J1/J3.21 J23.1 J23.2), MCU098_05_XDS110_Target_Interface (J101.4)
GND: MCU098_01_MSPM0G3507_Target_Device (33 pins), MCU098_02_BoosterPack_Connectors (23 pins), MCU098_05_XDS110_Target_Interface (6 pins)
XDS_GND: MCU098_03_XDS110_Debug_Probe (37 pins), MCU098_04_XDS110-ET_EnergyTrace (27 pins), MCU098_05_XDS110_Target_Interface (6 pins), MCU098_06_XDS110-ET_USB_Power (11 pins)
XDS_VCC: MCU098_03_XDS110_Debug_Probe (26 pins), MCU098_04_XDS110-ET_EnergyTrace (11 pins), MCU098_05_XDS110_Target_Interface (IC2.8 J102.1 R85.2), MCU098_06_XDS110-ET_USB_Power (5 pins)
3.3VM: MCU098_01_MSPM0G3507_Target_Device (J13.1), MCU098_02_BoosterPack_Connectors (R56.2 U2#1.8)
BSL_INVOKE: MCU098_03_XDS110_Debug_Probe (XDS1.42), MCU098_05_XDS110_Target_Interface (IC2.1 J101.17)
DCDCIO0: MCU098_03_XDS110_Debug_Probe (XDS1.5), MCU098_04_XDS110-ET_EnergyTrace (XDS2.4)
DCDCIO1: MCU098_03_XDS110_Debug_Probe (XDS1.6), MCU098_04_XDS110-ET_EnergyTrace (XDS2.5)
DCDCPULSE: MCU098_03_XDS110_Debug_Probe (XDS1.127), MCU098_04_XDS110-ET_EnergyTrace (R47.2 XDS2.3)
DCDCRST: MCU098_03_XDS110_Debug_Probe (TP1.1 XDS1.11), MCU098_04_XDS110-ET_EnergyTrace (C35.1 R45.1 XDS2.9)
DCDCTEST: MCU098_03_XDS110_Debug_Probe (TP3.1 XDS1.27), MCU098_04_XDS110-ET_EnergyTrace (R46.2 XDS2.10)
HOSTSCL: MCU098_03_XDS110_Debug_Probe (XDS1.49), MCU098_04_XDS110-ET_EnergyTrace (R42.1 XDS2.7)
HOSTSDA: MCU098_03_XDS110_Debug_Probe (XDS1.50), MCU098_04_XDS110-ET_EnergyTrace (R41.1 XDS2.8)
IRSTN: MCU098_03_XDS110_Debug_Probe (R33.1), MCU098_06_XDS110-ET_USB_Power (TP9.1)
ITCK: MCU098_03_XDS110_Debug_Probe (XDS1.100), MCU098_06_XDS110-ET_USB_Power (R92.2 TP6.1)
ITDI: MCU098_03_XDS110_Debug_Probe (XDS1.98), MCU098_06_XDS110-ET_USB_Power (TP8.1)
ITDO: MCU098_03_XDS110_Debug_Probe (XDS1.97), MCU098_06_XDS110-ET_USB_Power (TP7.1)
ITMS: MCU098_03_XDS110_Debug_Probe (XDS1.99), MCU098_06_XDS110-ET_USB_Power (R91.2 TP5.1)
PA0-: MCU098_01_MSPM0G3507_Target_Device (J9.2 R13.2), MCU098_02_BoosterPack_Connectors (J19.9)
PA1-: MCU098_01_MSPM0G3507_Target_Device (J12.2 R19.2), MCU098_02_BoosterPack_Connectors (J17.9)
PA2-: MCU098_01_MSPM0G3507_Target_Device (R9.1), MCU098_02_BoosterPack_Connectors (J17.1)
PA3-: MCU098_01_MSPM0G3507_Target_Device (R10.1), MCU098_02_BoosterPack_Connectors (J17.2)
PA4-: MCU098_01_MSPM0G3507_Target_Device (R11.1), MCU098_02_BoosterPack_Connectors (J17.3)
PA5-: MCU098_01_MSPM0G3507_Target_Device (R15.1), MCU098_02_BoosterPack_Connectors (J17.4)
PA6-: MCU098_01_MSPM0G3507_Target_Device (R17.1), MCU098_02_BoosterPack_Connectors (J17.5)
PA7_CLK-OUT: MCU098_01_MSPM0G3507_Target_Device (MSP1.49), MCU098_02_BoosterPack_Connectors (J17.6)
PA8_UART1-TX: MCU098_01_MSPM0G3507_Target_Device (MSP1.54), MCU098_02_BoosterPack_Connectors (J1/J3.4)
PA9_UART1-RX: MCU098_01_MSPM0G3507_Target_Device (MSP1.55), MCU098_02_BoosterPack_Connectors (J14.3)
PA10_UART0-TX_BP: MCU098_01_MSPM0G3507_Target_Device (J25.3), MCU098_02_BoosterPack_Connectors (J2/J4.34 R62.2)
PA10_UART0-TX_XDS: MCU098_01_MSPM0G3507_Target_Device (J25.1), MCU098_05_XDS110_Target_Interface (J101.10)
PA11_UART0-RX_BP: MCU098_01_MSPM0G3507_Target_Device (J26.3), MCU098_02_BoosterPack_Connectors (J2/J4.33 R63.2)
PA11_UART0-RX_XDS: MCU098_01_MSPM0G3507_Target_Device (J26.1), MCU098_05_XDS110_Target_Interface (J101.8)
PA12_CAN-TX: MCU098_01_MSPM0G3507_Target_Device (MSP1.5), MCU098_02_BoosterPack_Connectors (J2/J4.32 R64.2)
PA13_CAN-RX: MCU098_01_MSPM0G3507_Target_Device (MSP1.6), MCU098_02_BoosterPack_Connectors (J2/J4.31 R65.2)
PA14_TIMH0-C0: MCU098_01_MSPM0G3507_Target_Device (MSP1.7), MCU098_02_BoosterPack_Connectors (J17.7)
PA15_DAC-OUT: MCU098_01_MSPM0G3507_Target_Device (MSP1.8), MCU098_02_BoosterPack_Connectors (R55.1)
PA16_OPA1-OUT_ADC1.1: MCU098_01_MSPM0G3507_Target_Device (MSP1.9), MCU098_02_BoosterPack_Connectors (J15.1)
PA17_OPA1-IN-_ADC1.2: MCU098_01_MSPM0G3507_Target_Device (MSP1.10), MCU098_02_BoosterPack_Connectors (R82.2)
PA18-: MCU098_01_MSPM0G3507_Target_Device (J8.1 R23.1), MCU098_05_XDS110_Target_Interface (J101.18 U1.5)
PA18_OPA1-IN+_ADC1.3_GPAMP-IN-: MCU098_01_MSPM0G3507_Target_Device (MSP1.11 R23.2), MCU098_02_BoosterPack_Connectors (6 pins)
PA19_SWDIO: MCU098_01_MSPM0G3507_Target_Device (MSP1.12), MCU098_05_XDS110_Target_Interface (J101.14 J103.2 U1.7)
PA20_SWCLK: MCU098_01_MSPM0G3507_Target_Device (MSP1.13), MCU098_05_XDS110_Target_Interface (J101.16 J103.4 U1.6)
PA21-: MCU098_01_MSPM0G3507_Target_Device (R20.1), MCU098_02_BoosterPack_Connectors (J17.8)
PA22_OPA0-OUT_ADC0.7_GPAMP-OUT_COMP2-IN0+: MCU098_01_MSPM0G3507_Target_Device (J1.2 MSP1.18), MCU098_02_BoosterPack_Connectors (C46.2 R61.2 R84.2)
PA23-: MCU098_01_MSPM0G3507_Target_Device (R22.1), MCU098_02_BoosterPack_Connectors (J17.10)
PA24_OPA0-IN1-_ADC0.3: MCU098_01_MSPM0G3507_Target_Device (MSP1.25), MCU098_02_BoosterPack_Connectors (R80.2)
PA25_OPA0-IN1+_ADC0.2: MCU098_01_MSPM0G3507_Target_Device (MSP1.26), MCU098_02_BoosterPack_Connectors (J1/J3.2)
PA26_OPA0-IN0+_GPAMP-IN+_COMP0-IN0+: MCU098_01_MSPM0G3507_Target_Device (J3.2 MSP1.30), MCU098_02_BoosterPack_Connectors (J1/J3.5 R57.1)
PA27_OPA0-IN0-_COMP0-IN0-_TIMA2_FAL: MCU098_01_MSPM0G3507_Target_Device (J2.2 MSP1.31), MCU098_02_BoosterPack_Connectors (J1/J3.8)
PA28_TIMA2_C0: MCU098_01_MSPM0G3507_Target_Device (MSP1.35), MCU098_02_BoosterPack_Connectors (J2/J4.38)
PA29_TIMG10_C0: MCU098_01_MSPM0G3507_Target_Device (MSP1.36), MCU098_02_BoosterPack_Connectors (J21.1)
PA30_TIMG10_C1: MCU098_01_MSPM0G3507_Target_Device (MSP1.37), MCU098_02_BoosterPack_Connectors (J21.2)
PA31_TIMA2_C1: MCU098_01_MSPM0G3507_Target_Device (MSP1.39), MCU098_02_BoosterPack_Connectors (J2/J4.37)
PB0_SPI1-CS2: MCU098_01_MSPM0G3507_Target_Device (MSP1.47), MCU098_02_BoosterPack_Connectors (J2/J4.12)
PB1_TIMA1-C1: MCU098_01_MSPM0G3507_Target_Device (MSP1.48), MCU098_02_BoosterPack_Connectors (J2/J4.39)
PB2_I2C1-SCL: MCU098_01_MSPM0G3507_Target_Device (MSP1.50), MCU098_02_BoosterPack_Connectors (J1/J3.9 R59.2)
PB3_I2C1-SDA: MCU098_01_MSPM0G3507_Target_Device (MSP1.51), MCU098_02_BoosterPack_Connectors (J1/J3.10 R60.2)
PB4_TIMA1-C0: MCU098_01_MSPM0G3507_Target_Device (MSP1.52), MCU098_02_BoosterPack_Connectors (J2/J4.40)
PB5: MCU098_01_MSPM0G3507_Target_Device (MSP1.53), MCU098_02_BoosterPack_Connectors (J19.1)
PB6_SPI1-CS0: MCU098_01_MSPM0G3507_Target_Device (MSP1.58), MCU098_02_BoosterPack_Connectors (J2/J4.13)
PB7_SPI1-POCI: MCU098_01_MSPM0G3507_Target_Device (MSP1.59), MCU098_02_BoosterPack_Connectors (J2/J4.14)
PB8_SPI1-PICO: MCU098_01_MSPM0G3507_Target_Device (MSP1.60), MCU098_02_BoosterPack_Connectors (J2/J4.15)
PB9_SPI1-SCK: MCU098_01_MSPM0G3507_Target_Device (MSP1.61), MCU098_02_BoosterPack_Connectors (J1/J3.7)
PB10_TIMG0-C0: MCU098_01_MSPM0G3507_Target_Device (MSP1.62), MCU098_02_BoosterPack_Connectors (J19.2)
PB11_TIMG0-C1: MCU098_01_MSPM0G3507_Target_Device (MSP1.63), MCU098_02_BoosterPack_Connectors (J19.3)
PB12_TIMA0-C2_TIMA1-FAL: MCU098_01_MSPM0G3507_Target_Device (MSP1.64), MCU098_02_BoosterPack_Connectors (J2/J4.19)
PB13_TIMA0-C3: MCU098_01_MSPM0G3507_Target_Device (MSP1.1), MCU098_02_BoosterPack_Connectors (J2/J4.35)
PB14_TIMG10_IDX: MCU098_01_MSPM0G3507_Target_Device (MSP1.2), MCU098_02_BoosterPack_Connectors (J21.3)
PB15_UART2-TX_TIMG1-C0: MCU098_01_MSPM0G3507_Target_Device (MSP1.3), MCU098_02_BoosterPack_Connectors (J2/J4.17)
PB16_UART2-RX_TIMG1-C1: MCU098_01_MSPM0G3507_Target_Device (MSP1.4), MCU098_02_BoosterPack_Connectors (J2/J4.11)
PB17_ADC1.4_SPI1-CS1: MCU098_01_MSPM0G3507_Target_Device (MSP1.14), MCU098_02_BoosterPack_Connectors (J2/J4.18)
PB18_ADC1.5: MCU098_01_MSPM0G3507_Target_Device (MSP1.15), MCU098_02_BoosterPack_Connectors (R76.2)
PB19_OPA1-IN+_ADC1.6: MCU098_01_MSPM0G3507_Target_Device (MSP1.16), MCU098_02_BoosterPack_Connectors (R78.2)
PB20_TIMA0-C2: MCU098_01_MSPM0G3507_Target_Device (MSP1.19), MCU098_02_BoosterPack_Connectors (J2/J4.36)
PB21: MCU098_01_MSPM0G3507_Target_Device (MSP1.20 S2.3), MCU098_02_BoosterPack_Connectors (J19.4)
PB22: MCU098_01_MSPM0G3507_Target_Device (J5.1 MSP1.21), MCU098_02_BoosterPack_Connectors (J19.5)
PB23_TIMA0-FAL: MCU098_01_MSPM0G3507_Target_Device (MSP1.22), MCU098_02_BoosterPack_Connectors (J14.1 J19.6)
PB24_ADC0.5_COMP1-IN1+: MCU098_01_MSPM0G3507_Target_Device (MSP1.23), MCU098_02_BoosterPack_Connectors (J1/J3.6 J27.1)
PB25_ADC0.4_TIMA2-FAL: MCU098_01_MSPM0G3507_Target_Device (MSP1.27), MCU098_02_BoosterPack_Connectors (C47.1 R72.2 R74.2)
PB26: MCU098_01_MSPM0G3507_Target_Device (J6.1 MSP1.28), MCU098_02_BoosterPack_Connectors (J19.8)
PB27: MCU098_01_MSPM0G3507_Target_Device (J7.1 MSP1.29), MCU098_02_BoosterPack_Connectors (J19.10)
~{RST}: MCU098_01_MSPM0G3507_Target_Device (C6.1 MSP1.38 R2.1 S3.4), MCU098_02_BoosterPack_Connectors (J2/J4.16), MCU098_05_XDS110_Target_Interface (J101.12 J103.10 U1.2)
REF_MAIN_LDO: MCU098_03_XDS110_Debug_Probe (XDS1.128), MCU098_04_XDS110-ET_EnergyTrace (R51.1 R54.2)
REF_TARGET_VCC: MCU098_03_XDS110_Debug_Probe (XDS1.120), MCU098_04_XDS110-ET_EnergyTrace (R50.1 R53.2)
VBUS_DETECT: MCU098_03_XDS110_Debug_Probe (XDS1.1), MCU098_06_XDS110-ET_USB_Power (R87.2 R88.2)
VCCEN1: MCU098_03_XDS110_Debug_Probe (TP2.1 XDS1.78), MCU098_04_XDS110-ET_EnergyTrace (IC1.1 R49.2)
XDS_DM: MCU098_03_XDS110_Debug_Probe (XDS1.93), MCU098_06_XDS110-ET_USB_Power (IC3.5 USB2.2)
XDS_DP: MCU098_03_XDS110_Debug_Probe (XDS1.94), MCU098_06_XDS110-ET_USB_Power (IC3.4 USB2.3)
XDS_ID: MCU098_03_XDS110_Debug_Probe (XDS1.95), MCU098_06_XDS110-ET_USB_Power (IC3.2 USB2.4)
XDS_RESET_OUT: MCU098_03_XDS110_Debug_Probe (XDS1.40), MCU098_05_XDS110_Target_Interface (IC2.2 J101.11 J102.10 R85.1)
XDS_RXD: MCU098_03_XDS110_Debug_Probe (XDS1.33), MCU098_05_XDS110_Target_Interface (J101.9)
XDS_TCK_SWDCLK: MCU098_03_XDS110_Debug_Probe (XDS1.35), MCU098_05_XDS110_Target_Interface (IC2.6 J101.15 J102.4)
XDS_TDI: MCU098_03_XDS110_Debug_Probe (XDS1.38), MCU098_05_XDS110_Target_Interface (IC2.3 J102.8)
XDS_TDO_SWO: MCU098_03_XDS110_Debug_Probe (XDS1.37), MCU098_05_XDS110_Target_Interface (IC2.5 J102.6)
XDS_TMS_SWDIO: MCU098_03_XDS110_Debug_Probe (XDS1.36), MCU098_05_XDS110_Target_Interface (IC2.7 J101.13 J102.2)
XDS_TXD: MCU098_03_XDS110_Debug_Probe (XDS1.34), MCU098_05_XDS110_Target_Interface (J101.7)
XDS_VBUS: MCU098_03_XDS110_Debug_Probe (R28.1), MCU098_04_XDS110-ET_EnergyTrace (5 pins), MCU098_05_XDS110_Target_Interface (J101.3), MCU098_06_XDS110-ET_USB_Power (7 pins)
XDS_VCCTARGET: MCU098_04_XDS110-ET_EnergyTrace (C39.1 C40.1 IC1.4 R50.2), MCU098_05_XDS110_Target_Interface (J101.5)

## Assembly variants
Variant 1: not fitted C4 C7 C45 C46 C48 C49 C50 C51 C52 J18 R9 R10 R11 R15 R17 R20 R22 R27 R50 R53 R59 R60 R61 R66 R67 R68 R70 R74 TP1 TP2 TP3 TP4 TP5 TP6 TP7 TP8 TP9 TP10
